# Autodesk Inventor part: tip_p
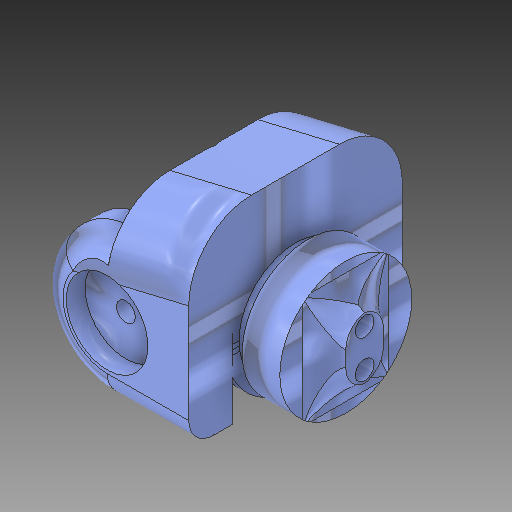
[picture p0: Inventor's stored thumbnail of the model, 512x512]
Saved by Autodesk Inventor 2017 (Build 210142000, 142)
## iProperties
Created: 2017-05
Part Number: tip_p
Material: Generic
Document SubType Name: Modeling
Designer: alez_
Density: 1 g/cm^3
Appearance: Default
Author: alez_
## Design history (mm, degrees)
derived "Tip.ipt" dims "d0" = 9
feature "Solid1::Tip.ipt" dims "d0" = 9
tag "TaggingFeature1"
body "Solid1"
